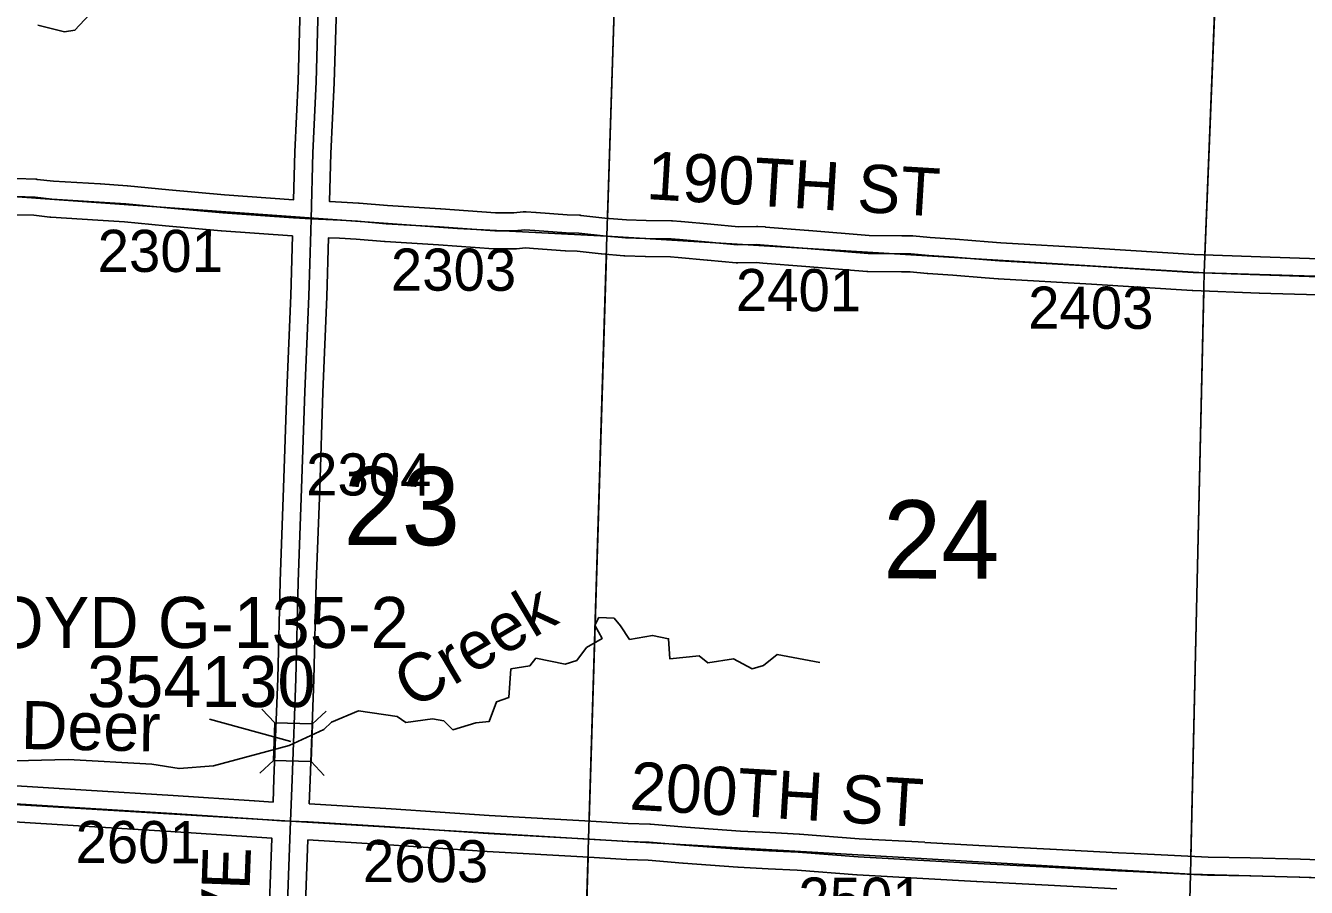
# Model space of a CAD drawing. Extents: x -157.2 to -99.3, y 12.2 to 46.2.
# Drawn here: x -136.661 to -134.532, y 30.661 to 32.094 of the extents above; entities that cross this region are included whole.
import ezdxf

# ---------------------------------------------------------------- set-up
doc = ezdxf.new("R2010")
doc.units = 0
for name, color, linetype in [('tdCoHydroRiver', 7, 'Continuous'), ('tdCoHydroTxtLg', 7, 'Continuous'), ('tdCoSecRdNmbr', 7, 'Continuous'), ('tdCoSecRdTxt', 7, 'Continuous'), ('tdCoSecRteBand', 7, 'Continuous'), ('tdCoSecRteCL', 7, 'Continuous'), ('tdCoSectLine', 7, 'Continuous'), ('tdCoSectLinePart', 7, 'Continuous'), ('tdCoSectNmbr', 7, 'Continuous'), ('tdCoStrucSec', 7, 'Continuous'), ('tdCoStrucSecCoName', 7, 'Continuous'), ('tdCoStrucSecFHWANum', 7, 'Continuous'), ('tdCoSurfEarth', 7, 'Continuous'), ('tdCoSurfGravel', 7, 'Continuous'), ('tdCoTwpBndry', 7, 'Continuous'), ('tdCoTwpBndryShd', 7, 'Continuous')]:
    doc.layers.add(name, color=color, linetype=linetype)

msp = doc.modelspace()

# ---------------------------------------------------------------- linework, layer by layer
at = {"layer": 'tdCoHydroRiver'}
for points in [[(-136.6402, 32.0949), (-136.5963, 32.084), (-136.5789, 32.0866), (-136.5544, 32.1127)], [(-136.7005, 30.8711), (-136.5899, 30.874), (-136.4512, 30.8664), (-136.4057, 30.8587), (-136.3487, 30.8632), (-136.2229, 30.8971), (-136.1653, 30.9238), (-136.1523, 30.936), (-136.1075, 30.9551), (-136.043, 30.9452), (-136.0291, 30.9353), (-135.9847, 30.9418), (-135.9659, 30.938), (-135.9506, 30.9233), (-135.9123, 30.9347), (-135.8902, 30.9372), (-135.8781, 30.97), (-135.8574, 30.9772), (-135.8543, 31.0245), (-135.8226, 31.0298), (-135.8127, 31.0422), (-135.7641, 31.0327), (-135.7449, 31.0384), (-135.7285, 31.06), (-135.7028, 31.075), (-135.7147, 31.0975), (-135.708, 31.1099), (-135.6827, 31.1091), (-135.6721, 31.0962), (-135.657, 31.0736), (-135.6189, 31.0803), (-135.5923, 31.0747), (-135.5901, 31.0414), (-135.5411, 31.0462), (-135.5272, 31.0347), (-135.4844, 31.0413), (-135.4533, 31.0245), (-135.4342, 31.0302), (-135.4115, 31.0484), (-135.3409, 31.0352)]]:
    msp.add_lwpolyline(points, dxfattribs=at)
at = {"layer": 'tdCoSecRteBand'}
for points in [[(-136.6766, 31.8398), (-136.6439, 31.8388), (-136.6427, 31.8388), (-136.6414, 31.8386), (-136.6144, 31.8355), (-136.5368, 31.8309), (-136.5366, 31.8309), (-136.5364, 31.8309), (-136.492, 31.8277), (-136.4917, 31.8276), (-136.4914, 31.8276), (-136.4228, 31.8212), (-136.3304, 31.8126), (-136.2155, 31.8046), (-136.2132, 31.8837), (-136.2132, 31.8839), (-136.2132, 31.8842), (-136.208, 32.0016), (-136.2043, 32.1251)], [(-136.1443, 32.1234), (-136.148, 31.9996), (-136.1481, 31.9994), (-136.1481, 31.9992), (-136.1532, 31.8818), (-136.1555, 31.8022), (-136.1555, 31.8016), (-136.1358, 31.8006), (-136.1358, 31.8006), (-136.1357, 31.8006), (-136.1076, 31.7991), (-136.1071, 31.7991), (-136.1066, 31.799), (-136.0594, 31.7949), (-135.971, 31.7895), (-135.9709, 31.7894), (-135.9707, 31.7894), (-135.8799, 31.7831), (-135.8494, 31.7829), (-135.8338, 31.7844), (-135.8314, 31.7847), (-135.829, 31.7845), (-135.8127, 31.7835), (-135.8125, 31.7835), (-135.8124, 31.7835), (-135.7605, 31.7798), (-135.7401, 31.7789), (-135.7392, 31.7788), (-135.7382, 31.7787), (-135.6981, 31.7743), (-135.6621, 31.7712), (-135.6294, 31.7703), (-135.5873, 31.7698), (-135.5864, 31.7698), (-135.5855, 31.7697), (-135.5717, 31.7687), (-135.5713, 31.7687), (-135.571, 31.7687), (-135.5222, 31.764), (-135.4762, 31.7599), (-135.4461, 31.7602), (-135.4451, 31.7602), (-135.4441, 31.7601), (-135.4315, 31.7594), (-135.4312, 31.7594), (-135.4309, 31.7593), (-135.3594, 31.7537), (-135.3593, 31.7537), (-135.3593, 31.7536), (-135.2589, 31.7453), (-135.2047, 31.7446), (-135.1898, 31.7449), (-135.1881, 31.7449), (-135.1864, 31.7447), (-135.1572, 31.7418), (-135.1158, 31.7394), (-135.1155, 31.7394), (-135.1152, 31.7393), (-135.0611, 31.7349), (-135.04, 31.7332), (-134.8855, 31.7241), (-134.8854, 31.7241), (-134.8854, 31.7241), (-134.7186, 31.7135), (-134.6086, 31.7096), (-134.5107, 31.7064)], [(-136.6941, 30.8311), (-136.5602, 30.8229), (-136.5601, 30.8229), (-136.5601, 30.8229), (-136.4156, 30.8141), (-136.4156, 30.8141), (-136.4155, 30.8141), (-136.2809, 30.8054), (-136.2807, 30.8054), (-136.2805, 30.8054), (-136.2494, 30.803), (-136.248, 30.8418), (-136.248, 30.8418), (-136.248, 30.8418), (-136.2418, 31.0088), (-136.2376, 31.1695), (-136.2376, 31.1696), (-136.2376, 31.1698), (-136.2319, 31.3258), (-136.2265, 31.4868), (-136.2265, 31.4869), (-136.2265, 31.487), (-136.2201, 31.6457), (-136.2172, 31.7446), (-136.2178, 31.7446), (-136.2178, 31.7446), (-136.2178, 31.7446), (-136.335, 31.7528), (-136.3353, 31.7528), (-136.3357, 31.7528), (-136.4284, 31.7614), (-136.4284, 31.7614), (-136.4284, 31.7614), (-136.4966, 31.7678), (-136.5405, 31.771), (-136.6188, 31.7757), (-136.6196, 31.7757), (-136.6204, 31.7758), (-136.647, 31.7789), (-136.6785, 31.7798)], [(-134.5128, 31.6464), (-134.6106, 31.6496), (-134.6106, 31.6496), (-134.6107, 31.6496), (-134.7211, 31.6536), (-134.7216, 31.6536), (-134.722, 31.6536), (-134.8891, 31.6642), (-135.0439, 31.6733), (-135.0442, 31.6734), (-135.0446, 31.6734), (-135.066, 31.6751), (-135.1197, 31.6795), (-135.1613, 31.682), (-135.1619, 31.682), (-135.1625, 31.6821), (-135.1906, 31.6848), (-135.2042, 31.6846), (-135.2046, 31.6846), (-135.205, 31.6846), (-135.2608, 31.6854), (-135.2618, 31.6854), (-135.2629, 31.6855), (-135.3642, 31.6938), (-135.4353, 31.6995), (-135.4466, 31.7002), (-135.4772, 31.6999), (-135.4786, 31.6999), (-135.48, 31.7), (-135.5276, 31.7042), (-135.5277, 31.7042), (-135.5279, 31.7042), (-135.5763, 31.7089), (-135.5889, 31.7098), (-135.6304, 31.7103), (-135.6307, 31.7103), (-135.6309, 31.7103), (-135.6647, 31.7113), (-135.6656, 31.7113), (-135.6664, 31.7114), (-135.7036, 31.7146), (-135.704, 31.7146), (-135.7043, 31.7146), (-135.7439, 31.719), (-135.7637, 31.7199), (-135.764, 31.7199), (-135.7643, 31.72), (-135.8165, 31.7237), (-135.8302, 31.7245), (-135.8451, 31.723), (-135.8467, 31.7228), (-135.8483, 31.7228), (-135.8813, 31.7231), (-135.8823, 31.7231), (-135.8832, 31.7232), (-135.9748, 31.7296), (-136.0634, 31.735), (-136.0638, 31.735), (-136.0642, 31.735), (-136.1113, 31.7392), (-136.1389, 31.7406), (-136.1572, 31.7416), (-136.1601, 31.6437), (-136.1601, 31.6436), (-136.1601, 31.6434), (-136.1665, 31.4847), (-136.172, 31.3238), (-136.172, 31.3237), (-136.172, 31.3237), (-136.1776, 31.1677), (-136.1818, 31.0071), (-136.1818, 31.0069), (-136.1818, 31.0068), (-136.188, 30.8396), (-136.1894, 30.8003), (-136.1892, 30.8003), (-136.0531, 30.7919), (-136.053, 30.7919), (-136.053, 30.7919), (-135.8901, 30.781), (-135.7213, 30.7712), (-135.6592, 30.7677), (-135.6231, 30.7663), (-135.6226, 30.7662), (-135.622, 30.7662), (-135.5636, 30.7615), (-135.4728, 30.7549), (-135.4238, 30.7523), (-135.3752, 30.7497), (-135.3748, 30.7497), (-135.3745, 30.7497), (-135.2752, 30.7421), (-135.1663, 30.7362), (-135.1662, 30.7361), (-135.1661, 30.7361), (-135.0767, 30.7307), (-134.9583, 30.7248), (-134.9582, 30.7248), (-134.9582, 30.7248), (-134.8443, 30.7189), (-134.8183, 30.7177), (-134.6954, 30.7118), (-134.6258, 30.7105), (-134.6256, 30.7105), (-134.6255, 30.7105), (-134.5421, 30.7081), (-134.5421, 30.7081), (-134.542, 30.7081), (-134.4799, 30.7061)], [(-136.2588, 30.5445), (-136.2531, 30.6975), (-136.2515, 30.7424), (-136.2515, 30.743), (-136.2849, 30.7456), (-136.4193, 30.7542), (-136.5638, 30.7631), (-136.6976, 30.7712)], [(-134.8474, 30.659), (-134.9613, 30.6649), (-135.0799, 30.6708), (-135.08, 30.6708), (-135.0802, 30.6708), (-135.1696, 30.6762), (-135.2788, 30.6822), (-135.2791, 30.6822), (-135.2794, 30.6822), (-135.3787, 30.6898), (-135.4269, 30.6924), (-135.4763, 30.695), (-135.4766, 30.695), (-135.4769, 30.695), (-135.5681, 30.7017), (-135.5682, 30.7017), (-135.5683, 30.7017), (-135.6262, 30.7063), (-135.6618, 30.7078), (-135.6621, 30.7078), (-135.6623, 30.7078), (-135.7247, 30.7113), (-135.7247, 30.7113), (-135.7248, 30.7113), (-135.8937, 30.7211), (-135.8938, 30.7211), (-135.8939, 30.7211), (-136.0569, 30.732), (-136.1916, 30.7403), (-136.1932, 30.6953), (-136.1932, 30.6953), (-136.1932, 30.6953), (-136.1989, 30.5422)]]:
    msp.add_lwpolyline(points, dxfattribs=at)
at = {"layer": 'tdCoSecRteCL'}
for points in [[(-136.1863, 31.7731), (-136.1832, 31.8828), (-136.178, 32.0005), (-136.1743, 32.1243), (-136.1704, 32.2666), (-136.1635, 32.4424), (-136.1578, 32.5884), (-136.1534, 32.7299), (-136.1515, 32.7728)], [(-136.6776, 31.8098), (-136.6448, 31.8088), (-136.617, 31.8056), (-136.5385, 31.8009), (-136.4942, 31.7977), (-136.4256, 31.7913), (-136.3329, 31.7827), (-136.2157, 31.7746), (-136.1863, 31.7731)], [(-136.2205, 30.7713), (-136.218, 30.8407), (-136.2118, 31.0079), (-136.2076, 31.1687), (-136.202, 31.3248), (-136.1965, 31.4858), (-136.1901, 31.6446), (-136.1869, 31.7531), (-136.1863, 31.7731)], [(-136.1863, 31.7731), (-136.1373, 31.7706), (-136.1092, 31.7691), (-136.0616, 31.7649), (-135.9728, 31.7595), (-135.8811, 31.7531), (-135.848, 31.7528), (-135.8308, 31.7546), (-135.8145, 31.7536), (-135.7622, 31.7499), (-135.7415, 31.7489), (-135.7011, 31.7445), (-135.6638, 31.7413), (-135.63, 31.7403), (-135.5876, 31.7398), (-135.5738, 31.7388), (-135.525, 31.7341), (-135.4774, 31.7299), (-135.4458, 31.7302), (-135.4333, 31.7294), (-135.3617, 31.7237), (-135.2604, 31.7154), (-135.2047, 31.7146), (-135.1894, 31.7149), (-135.1595, 31.7119), (-135.1176, 31.7094), (-135.0635, 31.705), (-135.0421, 31.7033), (-134.8873, 31.6942), (-134.7201, 31.6836), (-134.6096, 31.6796), (-134.5117, 31.6764)], [(-136.6959, 30.8011), (-136.562, 30.793), (-136.4175, 30.7841), (-136.2828, 30.7755), (-136.2355, 30.7718), (-136.2205, 30.7713)], [(-136.2559, 29.7717), (-136.2562, 29.7951), (-136.2523, 29.9216), (-136.2471, 30.0641), (-136.2409, 30.2259), (-136.2355, 30.3896), (-136.2288, 30.5433), (-136.2232, 30.6964), (-136.2205, 30.7713)], [(-136.2205, 30.7713), (-136.1911, 30.7703), (-136.0549, 30.7619), (-135.8919, 30.7511), (-135.723, 30.7412), (-135.6606, 30.7378), (-135.6244, 30.7363), (-135.5659, 30.7316), (-135.4747, 30.7249), (-135.4253, 30.7223), (-135.3768, 30.7198), (-135.2771, 30.7121), (-135.1679, 30.7062), (-135.0784, 30.7008), (-134.9598, 30.6949), (-134.8458, 30.6889), (-134.8198, 30.6877), (-134.6964, 30.6818), (-134.6264, 30.6805), (-134.543, 30.6781), (-134.4809, 30.6761)]]:
    msp.add_lwpolyline(points, dxfattribs=at)
at = {"layer": 'tdCoSectLine'}
for points in [[(-135.6946, 31.7439), (-135.6627, 32.7363)], [(-134.702, 31.6829), (-134.6624, 32.6731)], [(-136.6818, 31.81), (-135.9428, 31.7571), (-135.6946, 31.7439)], [(-135.7251, 30.7413), (-135.6946, 31.7439)], [(-135.6946, 31.7439), (-134.702, 31.6829)], [(-134.7248, 30.6831), (-134.702, 31.6829)], [(-134.702, 31.6829), (-133.725, 31.6539)], [(-136.7257, 30.8021), (-135.7251, 30.7413)], [(-135.755, 29.7387), (-135.7251, 30.7413)], [(-135.7251, 30.7413), (-134.7248, 30.6831)], [(-134.7505, 29.6994), (-134.7248, 30.6831)], [(-134.7248, 30.6831), (-134.3032, 30.6716), (-133.758, 30.6653)]]:
    msp.add_lwpolyline(points, dxfattribs=at)
at = {"layer": 'tdCoSectLinePart'}
for points in [[(-135.6936, 31.7743), (-135.6637, 32.706)], [(-134.7008, 31.7129), (-134.6636, 32.6431)], [(-135.7242, 30.7714), (-135.6955, 31.7142)], [(-134.7241, 30.7131), (-134.7027, 31.6529)], [(-135.7541, 29.7692), (-135.726, 30.7115)]]:
    msp.add_lwpolyline(points, dxfattribs=at)
at = {"layer": 'tdCoStrucSec'}
for p, q in [((-136.2467, 30.935), (-136.2681, 30.9578)), ((-136.1841, 30.933), (-136.1613, 30.9544)), ((-136.2487, 30.8724), (-136.2715, 30.851)), ((-136.1861, 30.8704), (-136.1647, 30.8476))]:
    msp.add_line(p, q, dxfattribs=at)
msp.add_lwpolyline([(-136.2487, 30.8724), (-136.2467, 30.935), (-136.1841, 30.933), (-136.1861, 30.8704)], close=True, dxfattribs=at)
at = {"layer": 'tdCoStrucSecFHWANum'}
msp.add_line((-136.355, 30.9408), (-136.2199, 30.9037), dxfattribs=at)
at = {"layer": 'tdCoSurfEarth'}
for points in [[(-135.0635, 31.705), (-135.0421, 31.7033), (-134.8873, 31.6942), (-134.7201, 31.6836), (-134.6096, 31.6796), (-134.5117, 31.6764), (-134.4301, 31.6732), (-134.3728, 31.6715), (-134.1453, 31.6664)], [(-135.4253, 30.7223), (-135.3768, 30.7198), (-135.2771, 30.7121), (-135.1679, 30.7062), (-135.0784, 30.7008), (-134.9598, 30.6949), (-134.8458, 30.6889), (-134.8198, 30.6877)], [(-134.8198, 30.6877), (-134.6964, 30.6818), (-134.6264, 30.6805), (-134.543, 30.6781), (-134.4809, 30.6761), (-134.3884, 30.6727), (-134.2794, 30.6709), (-134.1558, 30.6707), (-134.0663, 30.6692), (-133.9447, 30.6677), (-133.8661, 30.6675), (-133.7577, 30.6653)]]:
    msp.add_lwpolyline(points, dxfattribs=at)
at = {"layer": 'tdCoSurfGravel'}
for points in [[(-136.2559, 29.7717), (-136.2562, 29.7951), (-136.2523, 29.9216), (-136.2471, 30.0641), (-136.2409, 30.2259), (-136.2355, 30.3896), (-136.2288, 30.5433), (-136.2232, 30.6964), (-136.2205, 30.7713), (-136.218, 30.8407), (-136.2118, 31.0079), (-136.2076, 31.1687), (-136.202, 31.3248), (-136.1965, 31.4858), (-136.1901, 31.6446), (-136.1869, 31.7531), (-136.1863, 31.7731), (-136.1832, 31.8828), (-136.178, 32.0005), (-136.1743, 32.1243)], [(-136.6776, 31.8098), (-136.6448, 31.8088), (-136.617, 31.8056), (-136.5385, 31.8009), (-136.4942, 31.7977), (-136.4256, 31.7913), (-136.3329, 31.7827), (-136.2157, 31.7746), (-136.1863, 31.7731)], [(-136.1863, 31.7731), (-136.1373, 31.7706), (-136.1092, 31.7691), (-136.0616, 31.7649), (-135.9728, 31.7595), (-135.8811, 31.7531), (-135.848, 31.7528), (-135.8308, 31.7546), (-135.8145, 31.7536), (-135.7622, 31.7499), (-135.7415, 31.7489), (-135.7011, 31.7445), (-135.6638, 31.7413), (-135.63, 31.7403), (-135.5876, 31.7398), (-135.5738, 31.7388), (-135.525, 31.7341), (-135.4774, 31.7299), (-135.4458, 31.7302), (-135.4333, 31.7294), (-135.3617, 31.7237), (-135.2604, 31.7154), (-135.2047, 31.7146), (-135.1894, 31.7149), (-135.1595, 31.7119), (-135.1176, 31.7094), (-135.0635, 31.705)], [(-136.6959, 30.8011), (-136.562, 30.793), (-136.4175, 30.7841), (-136.2828, 30.7755), (-136.2355, 30.7718), (-136.2205, 30.7713)], [(-136.2205, 30.7713), (-136.2205, 30.7713), (-136.1911, 30.7703), (-136.0549, 30.7619), (-135.8919, 30.7511), (-135.723, 30.7412), (-135.6606, 30.7378), (-135.6244, 30.7363), (-135.5659, 30.7316), (-135.4747, 30.7249), (-135.4253, 30.7223)]]:
    msp.add_lwpolyline(points, dxfattribs=at)
at = {"layer": 'tdCoTwpBndry'}
for points in [[(-134.7008, 31.7129), (-134.6636, 32.6431)], [(-134.7241, 30.7131), (-134.7027, 31.6529)]]:
    msp.add_lwpolyline(points, dxfattribs=at)
at = {"layer": 'tdCoTwpBndryShd'}
msp.add_lwpolyline([(-134.5827, 34.8376), (-134.6206, 33.6622), (-134.6624, 32.6731), (-134.702, 31.6829), (-134.7248, 30.6831), (-134.7505, 29.6994), (-134.7778, 28.6994), (-134.8012, 27.7577), (-134.8314, 26.7672), (-134.8649, 25.7715), (-134.8895, 24.789), (-134.9097, 23.8132), (-134.9318, 22.8156), (-134.9713, 21.779), (-134.9998, 20.7866), (-135.0355, 19.7869), (-135.0694, 18.8043), (-135.1107, 17.815), (-135.1553, 16.8138)], dxfattribs=at)

# ---------------------------------------------------------------- texts
at = {"layer": 'tdCoHydroTxtLg'}
for s, rotation, p in [('Creek', 30.6709, (-136.017, 30.9565)), ('Deer', 358.9191, (-136.669, 30.8915))]:
    msp.add_text(s, height=0.08, rotation=rotation, dxfattribs=at).set_placement(p)
at = {"layer": 'tdCoSecRdNmbr'}
for s, rotation, p in [('2301', 359.8961, (-136.541, 31.6848)), ('2303', 359.8965, (-136.0537, 31.6536)), ('2401', 359.8969, (-135.4804, 31.6196)), ('2403', 359.8973, (-134.9946, 31.5903)), ('2304', 359.8964, (-136.1946, 31.3131)), ('2601', 359.8961, (-136.5778, 30.7018)), ('2603', 359.8965, (-136.1002, 30.6701)), ('2501', 359.897, (-135.3766, 30.6078))]:
    msp.add_text(s, height=0.07, rotation=rotation, dxfattribs=at).set_placement(p)
at = {"layer": 'tdCoSecRdTxt'}
for s, rotation, p in [('190TH ST', 356.5561, (-135.6303, 31.8059)), ('200TH ST', 356.5523, (-135.6581, 30.7908)), ('EMMETT AVE', 87.9406, (-136.311, 30.0325))]:
    msp.add_text(s, height=0.08, rotation=rotation, dxfattribs=at).set_placement(p)
at = {"layer": 'tdCoSectNmbr'}
for s, rotation, p in [('23', 359.8964, (-136.1324, 31.2305)), ('24', 359.897, (-135.2358, 31.175))]:
    msp.add_text(s, height=0.13, rotation=rotation, dxfattribs=at).set_placement(p)
at = {"layer": 'tdCoStrucSecCoName'}
msp.add_text('FLOYD G-135-2', height=0.085, dxfattribs=at).set_placement((-136.8517, 31.0593))
at = {"layer": 'tdCoStrucSecFHWANum'}
msp.add_text('354130', height=0.085, dxfattribs=at).set_placement((-136.5583, 30.9611))

doc.saveas('drawing.dxf')
